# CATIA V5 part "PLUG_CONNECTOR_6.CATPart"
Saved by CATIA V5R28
Part number: PLUG_CONNECTOR_6
Revision: ---
Publications: "MasterKeywayAxis", "InsertFrontFace", "InsertRearFace", "Logical Termination.1", "Logical Pin.1", "CCP", "Face_generated(CCP)", "Axis_generated(CCP)", "Face_generated(CCP).1", "BCP", "BCPRPoint_generated(BCP)", "BCPPlane_generated(BCP)", "BaCP", "Face_generated(BaCP)", "Face_generated(BaCP).1", "CaCP", "CaCPRPoint_generated(CaCP)", "Axis_generated(CaCP)", "Axis_generated(BaCP)", "Face"
Bounding box of the stored display mesh (mm): x 0 to 33.16, y -20.85 to 20.85, z -20.806 to 20.806
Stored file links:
  C:\Users\ajc8720\Documents\BOEING_WORK\0001-2CES\004-AP242\Boeing-Generic_Harness_R3\PLUG_CONNECTOR_6.CATPart
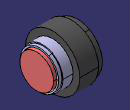
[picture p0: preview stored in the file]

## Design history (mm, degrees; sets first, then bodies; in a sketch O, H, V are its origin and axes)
Parameters
  PartNumber = "PLUG_CONNECTOR_6"
AxisSystem1 "MasterKeywayAxis": origin (0, 0, 0), X (1, 0, 0), Y (0, 1, 0), Z (0, 0, 1)
Set1 "EGF"
  Set2 "CCP"
    Point1 "CCPRPoint": (15.01 {= deleted_ShoulderFront}, 0, 0)
  Set3 "BaCP"
    Point2 "BaCPRPoint": (31 {= deleted_ShellLength}, 0, 0)
  Set4 "BCP"
    Plane1 "BCPPlane": type Offset, RefPlane face of Pad6, Offset 0, reversed
    Point3 "BCPRPoint": type OnPlane, Support Plane1, H 0, V 0, Direction (0, 1, 0)
  Set5 "CaCP"
    Point4 "CaCPRPoint": (15.01 {= deleted_ShoulderFront}, 0, 0)
Body1 "CouplingRing" (main body)
  Sketch1 on yz-plane, origin (0, 0, 0), H (0, 1, 0), V (0, 0, 1)
    circle A1 centre (0, 0) radius 20.85
    radius A1 = 20.85
  Pad1 "CouplingRing": profile Sketch1, direction (1, 0, 0), length 20.84 {= deleted_CouplingRingFront + deleted_CouplingRingLength}, opposite side length -1.68 {= -( deleted_CouplingRingFront )}
  Sketch2 on zx-plane, origin (0, 0, 0), H (-1, 0, 0), V (0, 0, 1)
    line L1 (-6.38, 20.85) -> (-1.68, 20.85)
    line L2 (-1.68, 20.85) -> (-1.68, 19.05)
    line L3 (-1.68, 19.05) -> (-6.38, 19.05)
    line L4 (-6.38, 19.05) -> (-6.38, 20.85)
    distance H L3 = 19.05
    distance H L1 = 20.85
    distance V L2 = 1.68
    length L1 = 4.7
    horizontal: L1 H, L3 H
    vertical: L2 V, L4 V
  Groove1 "CouplingRingRelief": profile Sketch2, axis Sketch2.H, angle 360
  Sketch3 on face of Pad1, origin (1.68, 0, 0), H (0, -1, 0), V (0, 0, 1)
    point P1 (0, 0)
    reference intersected line E1 through (0, 0) direction (-1, 0) from xy-plane
    reference intersected line E2 through (0, 0) direction (0, -1) from zx-plane
    coincidence: P1 E1, P1 E2
  Hole1 "CouplingRingID": placed by Sketch3, at (1.68, 0, 0) direction (1, 0, 0), diameter 35.28 {= deleted_CouplingRingThreadDia}, depth 18.3 {= deleted_CouplingRingThreadLength}, counterbore diameter 35.66 {= deleted_CouplingRingFrontID}, counterbore depth 2.14 {= deleted_CouplingRingFrontIDLength}
  Sketch4 on face of Hole1, origin (19.98, 0, 0), H (0, 1, 0), V (0, 0, -1)
    point P1 (0, 0)
    reference intersected line E1 through (0, 0) direction (0, 1) from zx-plane
    reference intersected line E2 through (0, 0) direction (1, 0) from xy-plane
    coincidence: P1 E1, P1 E2
  Hole2 "CouplingRingThruHole": placed by Sketch4, at (19.98, 0, 0) direction (1, 0, 0), diameter 31.4 {= deleted_CouplingRingThruDia}, through (limit type 6)
Body2 "Shell"
  Sketch5 on yz-plane, origin (0, 0, 0), H (0, 1, 0), V (0, 0, 1)
    circle A1 centre (0, 0) radius 14.67
    radius A1 = 14.67
  Pad2 "ShellFront": profile Sketch5, direction (1, 0, 0), length 15.01 {= deleted_ShoulderFront}
  Sketch6 on yz-plane, origin (0, 0, 0), H (0, 1, 0), V (0, 0, 1)
    circle A1 centre (0, 0) radius 15.5
    radius A1 = 15.5
  Pad3 "ShellBack": profile Sketch6, direction (1, 0, 0), length 31 {= deleted_ShellLength}, opposite side length -15.01 {= -( deleted_ShoulderFront )}
  Sketch7 on zx-plane, origin (0, 0, 0), H (-1, 0, 0), V (0, 0, 1)
    line L1 (-31, 15.5) -> (-23.89, 15.5)
    line L2 (-28.46, 15.5) -> (-28.46, 14.785)
    line L3 (-28.46, 14.785) -> (-31, 14.785)
    line L4 (-31, 14.785) -> (-31, 15.5)
    line L5 (-23.89, 15.5) -> (-23.89, 15.5)
    line L6 (-23.89, 15.5) -> (-28.46, 15.5)
    distance V L4 = 31
    length L1 = 7.11
    length L3 = 2.54
    distance H L3 = 14.785
    distance H L6 = 15.5
    distance L1 H = 15.5
    horizontal: L1 H, L3 H, L6 H
    vertical: L2 V, L4 V, L5 V
  Groove2 "AccyTeethThread": profile Sketch7, axis Sketch7.H, angle 360
  Sketch8 on yz-plane, origin (0, 0, 0), H (0, 1, 0), V (0, 0, 1)
    point P1 (-1.27, 0)
    line L1 (-1.27, 0) -> (1.27, 0)
    line L2 (1.27, 0) -> (1.27, 15.68)
    line L3 (1.27, 15.68) -> (-1.27, 15.68)
    line L4 (-1.27, 15.68) -> (-1.27, 0)
    length L3 = 2.54
    distance H L3 = 15.68
    coincidence: P1 H
    horizontal: L1 H, L3 H
    vertical: L2 V, L4 V
    symmetry: L2 L4 V
  Pad4 "MasterKeyway": profile Sketch8, direction (1, 0, 0), length 15.01 {= deleted_ShoulderFront}, opposite side length -0.76 {= - ( deleted_MasterKeyFront )}
  Sketch9 on face of Pad2, origin (0, 0, 0), H (0, -1, 0), V (0, 0, 1)
    point P1 (0, 0)
    reference intersected line E1 through (0, 0) direction (0, -1) from zx-plane
    reference intersected line E2 through (0, 0) direction (-1, 0) from xy-plane
    coincidence: P1 E1, P1 E2
  Hole3 "FrontShellID": placed by Sketch9, at (0, 0, 0) direction (1, 0, 0), diameter 25.6 {= deleted_ShellFrontID}, depth 20.46 {= deleted_ShellLength - deleted_ShellRearIDLength}
  Sketch10 on face of Pad3, origin (31, 0, 0), H (0, 1, 0), V (0, 0, 1)
    point P1 (0, 0)
    reference intersected line E1 through (0, 0) direction (0, 1) from zx-plane
    reference intersected line E2 through (0, 0) direction (-1, 0) from xy-plane
    coincidence: P1 E1, P1 E2
  Hole4 "RearShellID": placed by Sketch10, at (31, 0, 0) direction (-1, 0, 0), diameter 27.18 {= deleted_ShellRearID}, depth 10.54 {= deleted_ShellRearIDLength}
Body3 "Insert"
  Sketch11 on yz-plane, origin (0, 0, 0), H (0, 1, 0), V (0, 0, 1)
    circle A1 centre (0, 0) radius 12.585
    radius A1 = 12.585
  Pad5 "InsertOD": profile Sketch11, direction (1, 0, 0), length 20.46 {= deleted_InsertFront + deleted_InsertLength - deleted_GrommetLength}, opposite side length -0.1 {= -( deleted_InsertFront )}
  Sketch12 on yz-plane, origin (0, 0, 0), H (0, 1, 0), V (0, 0, 1)
    circle A1 centre (0, 0) radius 12.98
    radius A1 = 12.98
  Pad6 "GrommetOD": profile Sketch12, direction (1, 0, 0), length 33.16 {= deleted_InsertFront + deleted_InsertLength}, opposite side length -20.46 {= -( deleted_InsertFront + deleted_InsertLength - deleted_GrommetLength )}
Body4 "CCP"
  Sketch13 on face of Pad3, origin (15.01, 0, 0), H (0, 1, 0), V (0, 0, 1)
    arc A1 centre (0, 0) radius 1.016 from (-0.672, 0.762) to (0.672, 0.762) ccw
    line L1 (-0.672, 0.762) -> (0.672, 0.762)
    distance L1 H = 0.762
    radius A1 = 1.016
  Pad7: profile Sketch13, direction (1, 0, 0), length 0.508
Body5 "BaCP"
  Sketch14 on face of Pad3, origin (31, 0, 0), H (0, 1, 0), V (0, 0, 1)
    arc A1 centre (0, 0) radius 1.016 from (-0.672, 0.762) to (0.672, 0.762) ccw
    line L1 (-0.672, 0.762) -> (0.672, 0.762)
    distance L1 H = 0.762
    radius A1 = 1.016
  Sketch15 on face of Pad3, origin (31, 0, 0), H (0, 1, 0), V (0, 0, 1)
    circle A1 centre (0, 0) radius 1.27
    radius A1 = 1.27
  Pad8: profile Sketch15, direction (1, 0, 0), length 0.254, opposite side length 0.254
  Pocket1: profile Sketch14, direction (1, 0, 0), through (limit type 6)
